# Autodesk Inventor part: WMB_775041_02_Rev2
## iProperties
Created: 2008-12
Part Number: WMB_775041_02_Rev2
Document SubType Name: Modeling
Designer: WH
Density: 1 g/cm^3
Author: WH
Übersetzungsnorm: IGES 5.2
Dateiname: Z:\cad\Aktuell\Schwarzer\WMBM1\Änderung_November_08\WMB_775041_02_Rev2.igs
Vorprozessor: Cimatron E 8.
Postprozessor: Build: 538, Release: 2009 SR RTM - Date: Fri 08/29/2008
Gesendete Einheiten: MM
Unbestimmtheit: 0.0379984950907035
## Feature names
1. Basis1
